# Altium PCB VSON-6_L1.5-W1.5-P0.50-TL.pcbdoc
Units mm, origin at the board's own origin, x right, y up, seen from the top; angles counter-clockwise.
Board outline 14.95 x 14.31 mm, 2 copper layers (Top Layer, Bottom Layer), stack 0 mm thick; 1 components, 0 nets, 6 pads, 0 vias.
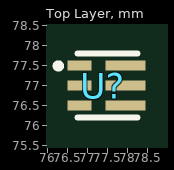
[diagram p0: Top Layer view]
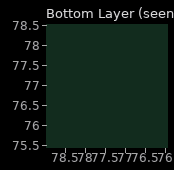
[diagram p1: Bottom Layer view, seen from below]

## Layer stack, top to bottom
Top Layer: signal copper (thickness not stored)
Bottom Layer: signal copper (thickness not stored)

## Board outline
84.8,69.85 69.85,69.85 69.85,84.16 84.8,84.16

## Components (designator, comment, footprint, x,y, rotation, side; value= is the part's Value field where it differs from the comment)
U? "" VSON-6_L1.5-W1.5-P0.50-TL 77.375,77 r0 top

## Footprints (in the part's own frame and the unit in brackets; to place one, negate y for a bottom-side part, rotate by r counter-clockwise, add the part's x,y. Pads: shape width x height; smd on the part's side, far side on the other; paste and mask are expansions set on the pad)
VSON-6_L1.5-W1.5-P0.50-TL [mm]
  rect 0.6x0.25 smd paste+0 mask+0.05: 1(-0.575,0.5) 2(-0.575,0) 3(-0.575,-0.5)
  rect 1x0.25 smd paste+0 mask+0.05: 4(0.575,-0.5) 5(0.575,0) 6(0.575,0.5)
  silkscreen extent -1.17,-0.8 0.87,0.8

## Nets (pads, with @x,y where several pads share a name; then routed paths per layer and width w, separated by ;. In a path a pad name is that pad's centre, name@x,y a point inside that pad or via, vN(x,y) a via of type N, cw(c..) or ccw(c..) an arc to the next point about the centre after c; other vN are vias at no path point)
pads on no net: U?.1 U?.2 U?.3 U?.4 U?.5 U?.6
